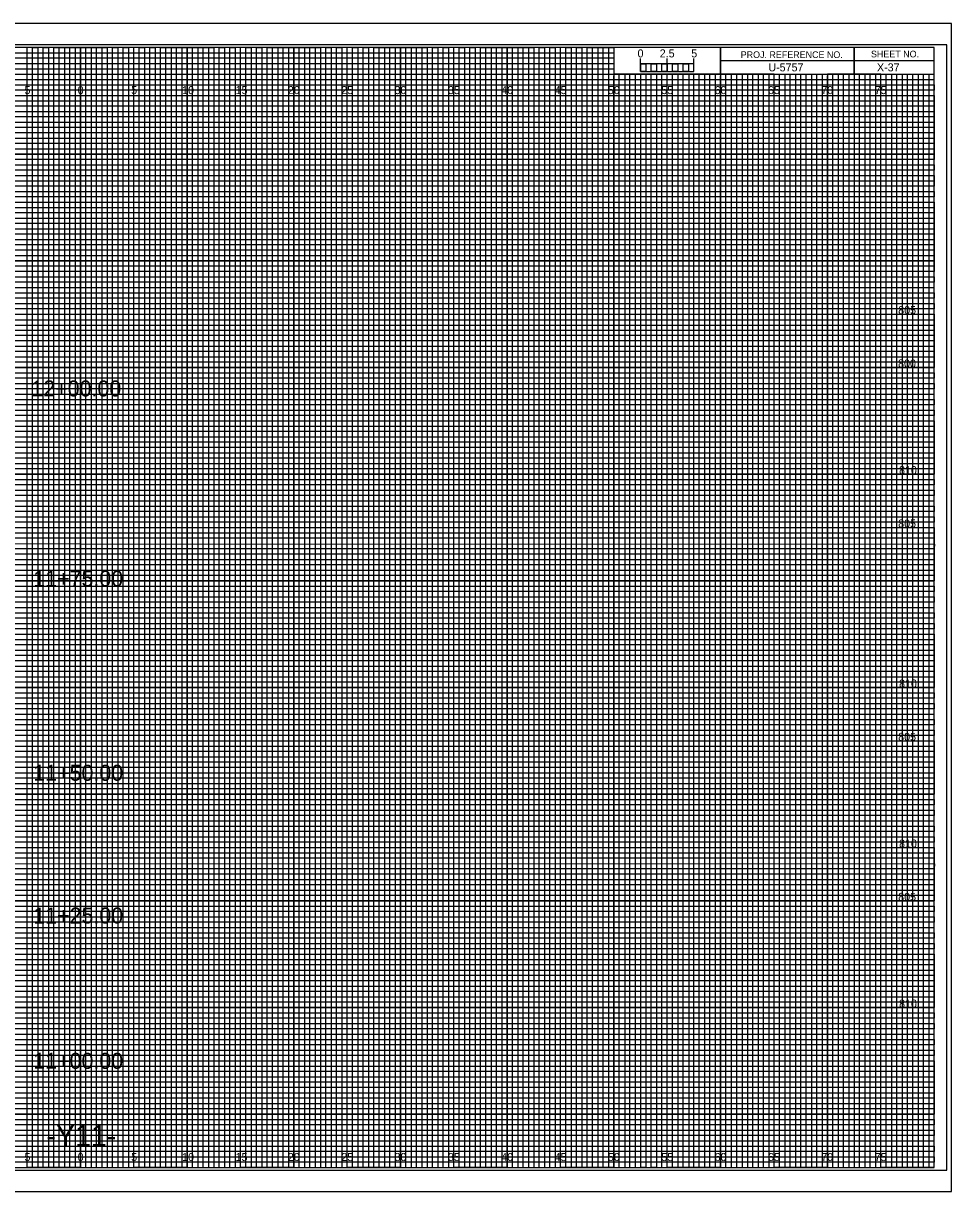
# Model space of a CAD drawing. Extents: x -7 to 162, y -2 to 107.
# Drawn here: x 74.6 to 161.7, y -2.3 to 107.3 of the extents above; entities that cross this region are included whole.
import ezdxf

# ---------------------------------------------------------------- set-up
doc = ezdxf.new("R2010")
doc.units = 0
for name, color, linetype in [('Exist Cross Section Cell', 7, 'Continuous'), ('Exist XS Center Line Elevation Label', 7, 'Continuous'), ('Prop CMT Pvmt Wedge Surface 1', 7, 'Continuous'), ('Prop CMT Pvmt Wedge Surface 2', 7, 'Continuous'), ('Prop CMT Pvmt Wedge Surface 3', 7, 'Continuous'), ('Prop XS Alignment Label', 7, 'Continuous'), ('Prop XS Bar Scale Labels', 7, 'Continuous'), ('Prop XS Elevation Labels', 7, 'Continuous'), ('Prop XS Hydro Elevations', 7, 'Continuous'), ('Prop XS Project Number', 7, 'Continuous'), ('Prop XS SE Text', 7, 'Continuous'), ('Prop XS Sheet Number', 7, 'Continuous'), ('Prop XS Side Slope Text', 7, 'Continuous'), ('Prop XS Station Labels', 7, 'Continuous'), ('Sheet Cross Section Grid Minor 2 CELL', 7, 'Continuous'), ('Sheet Cutting Line CELL', 7, 'Continuous'), ('Sheet DOT Grid CELL', 7, 'Continuous')]:
    doc.layers.add(name, color=color, linetype=linetype)

msp = doc.modelspace()

# ---------------------------------------------------------------- linework, layer by layer
at = {"layer": 'Exist Cross Section Cell'}
for p, q in [((75, 105), (70, 105)), ((75, 0), (75, 105)), ((85, 105), (80, 105)), ((80, 105), (80, 0)), ((85, 0), (85, 105)), ((95, 105), (90, 105)), ((90, 105), (90, 0)), ((95, 0), (95, 105)), ((105, 105), (100, 105)), ((100, 105), (100, 0)), ((105, 0), (105, 105)), ((115, 105), (110, 105)), ((110, 105), (110, 0)), ((115, 0), (115, 105)), ((125, 105), (120, 105)), ((120, 105), (120, 0)), ((125, 0), (125, 105)), ((130, 105), (130, 0)), ((135, 0), (135, 102.5)), ((145, 102.5), (140, 102.5)), ((140, 102.5), (140, 0)), ((145, 0), (145, 102.5)), ((155, 102.5), (150, 102.5)), ((150, 102.5), (150, 0)), ((155, 0), (155, 102.5)), ((80, 0), (75, 0)), ((90, 0), (85, 0)), ((100, 0), (95, 0)), ((110, 0), (105, 0)), ((120, 0), (115, 0)), ((130, 0), (125, 0)), ((140, 0), (135, 0)), ((150, 0), (145, 0)), ((160, 0), (155, 0)), ((160, 0), (160, 0))]:
    msp.add_line(p, q, dxfattribs=at)
for points in [[(0, 100), (160, 100), (160, 95), (0, 95)], [(0, 90), (160, 90), (160, 85), (0, 85)], [(0, 80), (160, 80), (160, 75), (0, 75)], [(0, 70), (160, 70), (160, 65), (0, 65)], [(0, 60), (160, 60), (160, 55), (0, 55)], [(0, 50), (160, 50), (160, 45), (0, 45)], [(0, 40), (160, 40), (160, 35), (0, 35)], [(0, 30), (160, 30), (160, 25), (0, 25)], [(0, 20), (160, 20), (160, 15), (0, 15)], [(0, 10), (160, 10), (160, 5), (0, 5)]]:
    msp.add_lwpolyline(points, dxfattribs=at)
at = {"layer": 'Exist XS Center Line Elevation Label'}
for points in [[(72.5, 0), (77.5, 0), (77.5, 105), (82.5, 105), (82.5, 0), (87.5, 0), (87.5, 105), (92.5, 105), (92.5, 0), (97.5, 0), (97.5, 105), (102.5, 105), (102.5, 0), (107.5, 0), (107.5, 105), (112.5, 105), (112.5, 0), (117.5, 0), (117.5, 105), (122.5, 105), (122.5, 0), (127.5, 0), (127.5, 105), (129.97, 105), (130, 105), (130, 102.5), (132.5, 102.5), (132.5, 0), (137.5, 0), (137.5, 102.5), (142.5, 102.5), (142.5, 0), (147.5, 0), (147.5, 102.5), (152.5, 102.5), (152.5, 0), (157.5, 0), (157.5, 102.5)], [(0, 102.5), (137.5, 102.5)], [(0, 92.5), (160, 92.5), (160, 97.5), (0, 97.5)], [(0, 82.5), (160, 82.5), (160, 87.5), (0, 87.5)], [(0, 72.5), (160, 72.5), (160, 77.5), (0, 77.5)], [(0, 62.5), (160, 62.5), (160, 67.5), (0, 67.5)], [(0, 52.5), (160, 52.5), (160, 57.5), (0, 57.5)], [(0, 42.5), (160, 42.5), (160, 47.5), (0, 47.5)], [(0, 32.5), (160, 32.5), (160, 37.5), (0, 37.5)], [(0, 22.5), (160, 22.5), (160, 27.5), (0, 27.5)], [(0, 12.5), (160, 12.5), (160, 17.5), (0, 17.5)], [(0, 2.5), (160, 2.5), (160, 7.5), (0, 7.5)]]:
    msp.add_lwpolyline(points, dxfattribs=at)
at = {"layer": 'Prop CMT Pvmt Wedge Surface 1'}
for p, q in [((132.5, 102.75), (132.5, 103.95)), ((132.5, 103.45), (132.5, 103.95)), ((135, 102.75), (135, 103.95)), ((137.5, 102.75), (137.5, 103.95)), ((137.5, 103.45), (137.5, 103.95))]:
    msp.add_line(p, q, dxfattribs=at)
for points in [[(137.5, 103.45), (132.5, 103.45), (132.5, 102.75), (137.5, 102.75)], [(132.5, 103.45), (133, 103.45), (133, 102.75), (132.5, 102.75)], [(133.5, 103.45), (134, 103.45), (134, 102.75), (133.5, 102.75)], [(134.5, 103.45), (135, 103.45), (135, 102.75), (134.5, 102.75)], [(135.5, 103.45), (136, 103.45), (136, 102.75), (135.5, 102.75)], [(136.5, 103.45), (137, 103.45), (137, 102.75), (136.5, 102.75)]]:
    msp.add_lwpolyline(points, close=True, dxfattribs=at)
at = {"layer": 'Prop CMT Pvmt Wedge Surface 2'}
msp.add_lwpolyline([(-6.7, -2.25), (161.65, -2.25), (161.65, 107.25), (-6.7, 107.25)], close=True, dxfattribs=at)
at = {"layer": 'Prop CMT Pvmt Wedge Surface 3'}
msp.add_lwpolyline([(-5.4, -0.25), (161.2, -0.25), (161.2, 105.25), (-5.4, 105.25)], close=True, dxfattribs=at)
at = {"layer": 'Prop XS Hydro Elevations'}
for p, q in [((152.5, 105), (152.5, 102.5)), ((152.5, 102.5), (152.5, 105)), ((160, 103.75), (140, 103.75)), ((140, 103.75), (140, 102.5)), ((140, 102.5), (160, 102.5))]:
    msp.add_line(p, q, dxfattribs=at)
for points in [[(160, 105), (0, 105), (0, 0), (160, 0)], [(140, 105), (130, 105), (130, 102.52), (140, 102.52)], [(160, 105), (140, 105), (140, 102.5), (160, 102.5)]]:
    msp.add_lwpolyline(points, close=True, dxfattribs=at)
at = {"layer": 'Prop XS Side Slope Text'}
for p, q in [((0, 104.5), (130, 104.5)), ((130, 104.5), (130, 103.99)), ((130, 103.99), (0, 103.99)), ((0, 103.5), (130, 103.5)), ((130, 102.95), (0, 102.95)), ((130, 103.5), (130, 102.95)), ((0, 102), (160, 102))]:
    msp.add_line(p, q, dxfattribs=at)
for points in [[(0, 101.5), (135, 101.5), (160, 101.5), (160, 101), (0, 101)], [(0, 100.5), (160, 100.5), (160, 99.5), (0, 99.5)], [(0, 99), (160, 99), (160, 98.5), (0, 98.49)], [(0, 98), (160, 98), (160, 97), (0, 97)], [(0, 96.5), (160, 96.5), (160, 96), (0, 96)], [(0, 95.5), (160, 95.5), (160, 94.5), (0, 94.5)], [(0, 94), (160, 94), (160, 93.5), (0, 93.5)], [(0, 93), (160, 93), (160, 92), (0, 92)], [(0, 91.5), (160, 91.5), (160, 91), (0, 91)], [(0, 90.5), (160, 90.5), (160, 89.5), (0, 89.5)], [(0, 89), (160, 89), (160, 88.5), (0, 88.5)], [(0, 88), (160, 88), (160, 86.98), (160, 86.5), (160, 86), (0, 86)], [(0, 87), (160, 87), (160, 86.5), (0, 86.5)], [(0, 85.5), (160, 85.5), (160, 84.5), (0, 84.52)], [(0, 84.52), (160, 84.5), (160, 84), (0, 84)], [(0, 83.5), (160, 83.5), (160, 83), (0, 83)], [(0, 82), (160, 82), (160, 81.5), (0, 81.5)], [(0, 81), (160, 81), (160, 80.5), (0, 80.5)], [(-0.04, 79.45), (160, 79.45), (160, 78.94), (-0.04, 78.94)], [(0, 78.5), (160, 78.5), (160, 78), (0, 78)], [(0, 77), (160, 77), (160, 76.5), (0, 76.5)], [(0, 76), (160, 76), (160, 75.5), (0, 75.5)], [(0, 74.5), (160, 74.5), (160, 74), (0, 74)], [(0, 73.5), (160, 73.5), (160, 73), (0, 73)], [(0, 72), (160, 72), (160, 71.5), (0, 71.5)], [(0, 71), (160, 71), (160, 70.5), (0, 70.5)], [(0, 69.5), (160, 69.5), (160, 68.99), (0, 69)], [(0, 68.5), (160, 68.5), (160, 68), (0, 68)], [(0, 67), (160, 67), (160, 66.5), (0, 66.5)], [(0, 66), (160, 66), (160, 65.5), (0, 65.5)], [(0, 64.5), (160, 64.5), (160, 64), (0, 64)], [(0, 63.5), (160, 63.5), (160, 63), (0, 63)], [(0, 62), (160, 62), (160, 61.5), (0, 61.5)], [(0, 61), (160, 61), (160, 60.5), (0, 60.5)], [(0, 59.5), (160, 59.5), (160, 59), (0, 59)], [(0, 58.5), (160.03, 58.45), (160, 58), (0, 58)], [(0, 57), (160, 57), (160, 56.5), (0, 56.5)], [(0, 56), (160, 56), (160, 55.5), (0, 55.5)], [(0, 54.5), (160, 54.5), (160, 54), (0, 54)], [(0, 53.5), (160, 53.5), (160, 53), (0, 53)], [(0, 52), (160, 52), (160, 51.5), (0, 51.5)], [(0, 51), (160, 51), (160, 50.5), (0, 50.5)], [(0, 49.5), (160, 49.5), (160, 49), (0, 49)], [(0, 48.5), (160, 48.5), (160, 48), (0, 48)], [(0, 47), (160, 47), (160, 46.5), (0, 46.5)], [(0, 46), (160, 46), (160, 45.5), (0, 45.5)], [(0, 44.5), (160, 44.5), (160, 44), (0, 44)], [(0, 43.5), (160, 43.5), (160, 43), (0, 43)], [(0, 42), (160, 42), (160, 41.5), (0, 41.5)], [(0, 41), (160, 41), (160, 40.5), (0, 40.5)], [(0, 39.5), (160, 39.5), (160, 38.99), (0, 39)], [(0, 38.5), (160, 38.5), (160, 38), (0, 38)], [(0, 37), (160, 37), (160, 36.5), (0, 36.5)], [(0, 36), (160, 36), (160, 35.5), (0, 35.5)], [(0, 34.5), (160, 34.5), (160, 34), (0, 34)], [(0, 33.5), (160, 33.5), (160, 33), (0, 33)], [(0, 32), (160, 32), (160, 31.5), (0, 31.5)], [(0, 31), (160, 31), (160, 30.5), (0, 30.5)], [(0, 29.5), (160, 29.5), (160, 29), (0, 29)], [(0, 28.5), (160.03, 28.46), (160, 28), (0, 28)], [(0, 27), (160, 27), (160, 26.5), (0, 26.5)], [(0, 26), (160, 26), (160, 25.5), (0, 25.5)], [(0, 24.5), (160, 24.5), (160, 24), (0, 24)], [(0, 23.5), (160, 23.5), (160, 23), (0, 23)], [(0, 22), (160, 22), (160, 21.5), (0, 21.5)], [(0, 21), (160, 21), (160, 20.5), (0, 20.5)], [(0, 19.5), (160, 19.5), (160, 19), (0, 19)], [(0, 18.5), (160, 18.5), (160, 18), (0, 18)], [(0, 17), (160, 17), (160, 16.5), (0, 16.5)], [(0, 16), (160, 16), (160, 15.5), (0, 15.5)], [(0, 14.5), (160, 14.5), (160, 14), (0, 14)], [(0, 13.5), (160, 13.5), (160, 13), (0, 13)], [(0, 12), (160, 12), (160, 11.5), (0, 11.5)], [(0, 11), (160, 11), (160, 10.5), (0, 10.5)], [(0, 9.5), (160, 9.5), (160, 9), (0, 9)], [(0, 8.5), (160, 8.5), (160, 8), (0, 8)], [(0, 7), (160, 7), (160, 6.5), (0, 6.5)], [(0, 6), (160, 6), (160, 5.5), (0, 5.5)], [(0, 4.5), (160, 4.5), (160, 4), (0, 4)], [(0, 3.5), (160, 3.5), (160, 3), (0, 3)], [(0, 2), (160, 2), (160, 1.5), (0, 1.5)], [(0, 1), (160, 1), (160, 0.5), (0, 0.5)]]:
    msp.add_lwpolyline(points, dxfattribs=at)
at = {"layer": 'Sheet Cross Section Grid Minor 2 CELL'}
for p, q in [((133.5, 102.5), (133, 102.5)), ((133, 102.5), (133, 0)), ((133.5, 0), (133.5, 102.5)), ((134.5, 102.5), (134, 102.5)), ((134, 102.5), (134, 0)), ((134.5, 0), (134.5, 102.5)), ((133, 0), (132.5, 0)), ((134, 0), (133.5, 0))]:
    msp.add_line(p, q, dxfattribs=at)
for points in [[(75, 0), (75.5, 0), (75.5, 105), (76, 105), (76, 0)], [(76, 0), (76.5, 0), (76.5, 105), (77, 105), (77, 0)], [(77.5, 0), (78, 0), (78, 105), (78.5, 105), (78.5, 0)], [(78.5, 0), (79, 0), (79, 105), (79.5, 105), (79.5, 0)], [(80, 0), (80.5, 0), (80.5, 105), (81, 105), (81, 0)], [(81, 0), (81.5, 0), (81.5, 105), (82, 105), (82, 0)], [(82.5, 0), (83, 0), (83, 105), (83.5, 105), (83.5, 0)], [(83.5, 0), (84, 0), (84, 105), (84.5, 105), (84.5, 0)], [(85, 0), (85.5, 0), (85.5, 105), (86, 105), (86, 0)], [(86, 0), (86.5, 0), (86.5, 105), (87, 105), (87, 0)], [(87.5, 0), (88, 0), (88, 105), (88.5, 105), (88.5, 0)], [(88.5, 0), (89, 0), (89, 105), (89.5, 105), (89.5, 0)], [(90, 0), (90.5, 0), (90.5, 105), (91, 105), (91, 0)], [(91, 0), (91.5, 0), (91.5, 105), (92, 105), (92, 0)], [(92.5, 0), (93, 0), (93, 105), (93.5, 105), (93.5, 0)], [(93.5, 0), (94, 0), (94, 105), (94.5, 105), (94.5, 0)], [(95, 0), (95.5, 0), (95.5, 105), (96, 105), (96, 0)], [(96, 0), (96.5, 0), (96.5, 105), (97, 105), (97, 0)], [(97.5, 0), (98, 0), (98, 105), (98.5, 105), (98.5, 0)], [(98.5, 0), (99, 0), (99, 105), (99.5, 105), (99.5, 0)], [(100, 0), (100.5, 0), (100.5, 105), (101, 105), (101, 0)], [(101, 0), (101.5, 0), (101.5, 105), (102, 105), (102, 0)], [(102.5, 0), (103, 0), (103, 105), (103.5, 105), (103.5, 0)], [(103.5, 0), (104, 0), (104, 105), (104.5, 105), (104.5, 0)], [(105, 0), (105.5, 0), (105.5, 105), (106, 105), (106, 0)], [(106, 0), (106.5, 0), (106.5, 105), (107, 105), (107, 0)], [(107.5, 0), (108, 0), (108, 105), (108.5, 105), (108.5, 0)], [(108.5, 0), (109, 0), (109, 105), (109.5, 105), (109.5, 0)], [(110, 0), (110.5, 0), (110.5, 105), (111, 105), (111, 0)], [(111, 0), (111.5, 0), (111.5, 105), (112, 105), (112, 0)], [(112.5, 0), (113, 0), (113, 105), (113.5, 105), (113.5, 0)], [(113.5, 0), (114, 0), (114, 105), (114.5, 105), (114.5, 0)], [(115, 0), (115.5, 0), (115.5, 105), (116, 105), (116, 0)], [(116, 0), (116.5, 0), (116.5, 105), (117, 105), (117, 0)], [(117.5, 0), (118, 0), (118, 105), (118.5, 105), (118.5, 0)], [(118.5, 0), (119, 0), (119, 105), (119.5, 105), (119.5, 0)], [(120, 0), (120.5, 0), (120.5, 105), (121, 105), (121, 0)], [(121, 0), (121.5, 0), (121.5, 105), (122, 105), (122, 0)], [(122.5, 0), (123, 0), (123, 105), (123.5, 105), (123.5, 0)], [(123.5, 0), (124, 0), (124, 105), (124.5, 105), (124.5, 0)], [(125, 0), (125.5, 0), (125.5, 105), (126, 105), (126, 0)], [(126, 0), (126.5, 0), (126.5, 105), (127, 105), (127, 0)], [(127.5, 0), (128, 0), (128, 105), (128.5, 105), (128.5, 0)], [(128.5, 0), (129, 0), (129, 105), (129.5, 105), (129.5, 0)], [(130, 0), (130.5, 0), (130.5, 102.5), (131.01, 102.5), (131.01, 0)], [(131, 0), (131.5, 0), (131.5, 102.5), (132, 102.5), (132, 0)], [(135, 0), (135.49, 0), (135.49, 102.5), (136, 102.5), (136, 0)], [(136, 0), (136.5, 0), (136.5, 102.5), (137.03, 102.5), (137.03, 0)], [(137.5, 0), (138, 0), (138, 102.5), (138.5, 102.5), (138.5, 0)], [(138.5, 0), (139, 0), (139, 102.5), (139.5, 102.5), (139.5, 0)], [(140, 0), (140.5, 0), (140.5, 102.5), (141, 102.5), (141, 0)], [(141, 0), (141.5, 0), (141.5, 102.5), (142, 102.5), (142, 0)], [(142.5, 0), (143, 0), (143, 102.5), (143.5, 102.5), (143.5, 0)], [(143.5, 0), (144, 0), (144, 102.5), (144.5, 102.5), (144.5, 0)], [(145, 0), (145.5, 0), (145.5, 102.5), (146, 102.5), (146, 0)], [(146, 0), (146.5, 0), (146.5, 102.5), (147, 102.5), (147, 0)], [(147.5, 0), (148, 0), (148, 102.5), (148.5, 102.5), (148.5, 0)], [(148.5, 0), (149, 0), (149, 102.5), (149.5, 102.5), (149.5, 0)], [(150, 0), (150.5, 0), (150.5, 102.5), (151, 102.5), (151, 0)], [(151, 0), (151.5, 0), (151.5, 102.5), (152, 102.5), (152, 0)], [(152.5, 0), (153, 0), (153, 102.5), (153.5, 102.5), (153.5, 0)], [(153.5, 0), (154, 0), (154, 102.5), (154.5, 102.5), (154.5, 0)], [(155, 0), (155.5, 0), (155.5, 102.5), (156, 102.5), (156, 0)], [(156, 0), (156.5, 0), (156.5, 102.5), (157, 102.5), (157, 0)], [(157.5, 0), (158, 0), (158, 102.5), (158.5, 102.5), (158.5, 0)], [(158.5, 0), (159, 0), (159, 102.5), (159.5, 102.5), (159.5, 0)]]:
    msp.add_lwpolyline(points, dxfattribs=at)
at = {"layer": 'Sheet Cutting Line CELL'}
for p, q in [((161.65, 107.25), (-6.7, 107.25)), ((-6.7, -2.25), (161.65, -2.25))]:
    msp.add_line(p, q, dxfattribs=at)
at = {"layer": 'Sheet DOT Grid CELL'}
for p, q in [((75, 0), (75, 105)), ((80, 0), (80, 105)), ((85, 0), (85, 105)), ((90, 0), (90, 105)), ((95, 0), (95, 105)), ((100, 0), (100, 105)), ((105, 0), (105, 105)), ((110, 0), (110, 105)), ((115, 0), (115, 105)), ((120, 0), (120, 105)), ((125, 0), (125, 105)), ((130, 0), (130, 102.34)), ((135, 0), (135, 102.34)), ((140, 0), (140, 102.34)), ((145, 0), (145, 102.34)), ((150, 0), (150, 102.34)), ((155, 0), (155, 102.34)), ((0, 100), (160, 100)), ((0, 95), (160, 95)), ((0, 90), (160, 90)), ((0, 85), (160, 85)), ((0, 80), (160, 80)), ((0, 75), (160, 75)), ((0, 70), (160, 70)), ((0, 65), (160, 65)), ((0, 60), (160, 60)), ((0, 55), (160, 55)), ((0, 50), (160, 50)), ((0, 45), (160, 45)), ((0, 40), (160, 40)), ((0, 35), (160, 35)), ((0, 30), (160, 30)), ((0, 25), (160, 25)), ((0, 20), (160, 20)), ((0, 15), (160, 15)), ((0, 10), (160, 10)), ((0, 5), (160, 5))]:
    msp.add_line(p, q, dxfattribs=at)

# ---------------------------------------------------------------- texts
at = {"layer": 'Prop CMT Pvmt Wedge Surface 1'}
msp.add_text('0', height=0.75, dxfattribs=at).set_placement((132.21, 104.06))
at = {"layer": 'Prop XS Alignment Label'}
msp.add_text('-Y11-', height=2, dxfattribs=at).set_placement((76.81, 2))
at = {"layer": 'Prop XS Bar Scale Labels'}
for s, p in [('2.5', (134.29, 104.06)), ('5', (137.24, 104.06))]:
    msp.add_text(s, height=0.75, dxfattribs=at).set_placement(p)
at = {"layer": 'Prop XS Elevation Labels'}
for s, p in [('805', (156.64, 80)), ('800', (156.63, 75)), ('810', (156.72, 65)), ('805', (156.64, 60)), ('810', (156.72, 45)), ('805', (156.64, 40)), ('810', (156.72, 30)), ('805', (156.64, 25)), ('810', (156.72, 15))]:
    msp.add_text(s, height=0.75, dxfattribs=at).set_placement(p)
at = {"layer": 'Prop XS Hydro Elevations'}
for s, p in [('PROJ. REFERENCE NO.', (141.88, 104)), ('SHEET NO.', (154.09, 104.06))]:
    msp.add_text(s, height=0.625, dxfattribs=at).set_placement(p)
at = {"layer": 'Prop XS Project Number'}
msp.add_text('U-5757', height=0.75, dxfattribs=at).set_placement((144.47, 102.75))
at = {"layer": 'Prop XS SE Text'}
for s, p in [('5', (74.74, 100.62)), ('0', (79.73, 100.62)), ('0', (79.73, 100.62)), ('5', (84.74, 100.62)), ('10', (89.52, 100.62)), ('15', (94.53, 100.62)), ('20', (99.43, 100.62)), ('25', (104.44, 100.62)), ('30', (109.43, 100.62)), ('35', (114.44, 100.62)), ('40', (119.43, 100.62)), ('45', (124.44, 100.62)), ('50', (129.43, 100.62)), ('55', (134.44, 100.62)), ('60', (139.43, 100.62)), ('65', (144.44, 100.62)), ('70', (149.43, 100.62)), ('75', (154.44, 100.62)), ('5', (74.74, 0.62)), ('0', (79.73, 0.62)), ('0', (79.73, 0.62)), ('5', (84.74, 0.62)), ('10', (89.52, 0.62)), ('15', (94.53, 0.62)), ('20', (99.43, 0.62)), ('25', (104.44, 0.62)), ('30', (109.43, 0.62)), ('35', (114.44, 0.62)), ('40', (119.43, 0.62)), ('45', (124.44, 0.62)), ('50', (129.43, 0.62)), ('55', (134.44, 0.62)), ('60', (139.43, 0.62)), ('65', (144.44, 0.62)), ('70', (149.43, 0.62)), ('75', (154.44, 0.62))]:
    msp.add_text(s, height=0.75, dxfattribs=at).set_placement(p)
at = {"layer": 'Prop XS Sheet Number'}
msp.add_text('X-37', height=0.75, dxfattribs=at).set_placement((154.65, 102.75))
at = {"layer": 'Prop XS Station Labels'}
for s, p in [('12+00.00', (75.39, 72.28)), ('11+75.00', (75.57, 54.46)), ('11+50.00', (75.57, 36.26)), ('11+25.00', (75.57, 22.88)), ('11+00.00', (75.57, 9.26))]:
    msp.add_text(s, height=1.5, dxfattribs=at).set_placement(p)

doc.saveas('drawing.dxf')
